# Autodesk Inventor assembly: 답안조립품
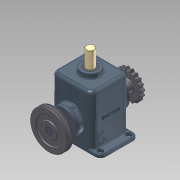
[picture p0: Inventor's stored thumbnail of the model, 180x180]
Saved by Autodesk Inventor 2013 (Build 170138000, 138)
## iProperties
Created: 2015-01
Part Number: 답안조립품
Document SubType Name: Assembly
Designer: hanacad7
Author: hanacad7
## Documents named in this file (15)
- C:\Documents and Settings\hanacad7\바탕 화면\350106V1007\답안조립품.iam
- C:\Documents and Settings\hanacad7\바탕 화면\350106V1007\본체.ipt
- C:\Documents and Settings\hanacad7\바탕 화면\350106V1007\M4x0.5.ipt
- C:\Documents and Settings\hanacad7\바탕 화면\350106V1007\베어링 6205.ipt
- C:\Documents and Settings\hanacad7\바탕 화면\350106V1007\체인 스프로킷.ipt
- C:\Documents and Settings\hanacad7\바탕 화면\350106V1007\커버.ipt
- C:\Documents and Settings\hanacad7\바탕 화면\350106V1007\멈춤나사 M5x0.5.ipt
- C:\Documents and Settings\hanacad7\바탕 화면\350106V1007\멈춤링.ipt
- C:\Documents and Settings\hanacad7\바탕 화면\350106V1007\오일실.ipt
- C:\Documents and Settings\hanacad7\바탕 화면\350106V1007\키 8x8.ipt
- C:\Documents and Settings\hanacad7\바탕 화면\350106V1007\편심축.ipt
- C:\Documents and Settings\hanacad7\바탕 화면\350106V1007\V-벨트풀리.ipt
- C:\Documents and Settings\hanacad7\바탕 화면\350106V1007\부시.ipt
- C:\Documents and Settings\hanacad7\바탕 화면\350106V1007\슬라이드.ipt
- C:\Documents and Settings\hanacad7\바탕 화면\350106V1007\가변 스프링.ipt
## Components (9 placed, 4 different names)
1. 5-체인 스프로킷:1 — 각도:3
2. V-벨트풀리:1 — 각도:2
3. 가변 스프링:1
4. M4x0.5:1
5. M4x0.5:2
6. M4x0.5:3
7. M4x0.5:4
8. M4x0.5:5
9. M4x0.5:6
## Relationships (2: Angle 2)
- 각도:2 [Angle]: V-벨트풀리:1
- 각도:3 [Angle]: 5-체인 스프로킷:1
